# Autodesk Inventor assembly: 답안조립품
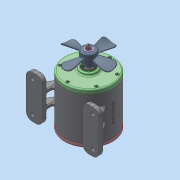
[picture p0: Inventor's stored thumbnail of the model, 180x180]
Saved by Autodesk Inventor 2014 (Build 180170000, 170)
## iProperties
Created: 2024-02
Part Number: 답안조립품
Document SubType Name: Assembly
Designer: dg
Author: dg
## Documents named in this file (20)
- C:\Users\dg\Desktop\640204V1010\답안조립품.iam
- C:\Users\dg\Desktop\640204V1010\본체.ipt
- C:\Users\dg\Desktop\640204V1010\뒷커버.ipt
- C:\Users\dg\Desktop\640204V1010\베어링 608.ipt
- C:\Users\dg\Desktop\640204V1010\오일 실 8 22 7.ipt
- C:\Users\dg\Desktop\640204V1010\육각 소켓 머리 볼트 M4 x 12.ipt
- C:\Users\dg\Desktop\640204V1010\메인 기어 축.ipt
- C:\Users\dg\Desktop\640204V1010\서브 기어 축.ipt
- C:\Users\dg\Desktop\640204V1010\베어링 6903.ipt
- C:\Users\dg\Desktop\640204V1010\앞커버.ipt
- C:\Users\dg\Desktop\640204V1010\오일 실 17 30 8.ipt
- C:\Users\dg\Desktop\640204V1010\키 5 x 5 x 24.ipt
- C:\Users\dg\Desktop\640204V1010\팬날개.ipt
- 팬날개.ipt
- C:\Users\dg\Desktop\640204V1010\스프링 와셔 M6.ipt
- C:\Users\dg\Desktop\640204V1010\육각 소켓 머리 볼트 M6 x 12.ipt
- C:\Users\dg\Desktop\640204V1010\부시.ipt
- C:\Users\dg\Desktop\640204V1010\슬라이더.ipt
- C:\Users\dg\Desktop\640204V1010\가변스프링.ipt
- C:\Users\dg\Desktop\640204V1010\앤드 캡.ipt
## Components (1 placed, 1 different names)
1. 가변스프링:1
